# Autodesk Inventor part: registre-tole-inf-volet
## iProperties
Author: chr
Created: 2001-06
Part Number: registre-tole-inf-volet
Material: Par défaut
Document SubType Name: Tôlerie
Designer: chr
Control State: 0
Master: False
Checked Out: False
PropertySet Name: Design Tracking Control
Shininess: 21.0
PropertySet Name: _Private Model Information
Length Units: 11269
Angle Units: 11286
Time Units: 11279
Mass Units: 11290
Length Display Precision: 3
Angle Display Precision: 2
Compacted: False
Density: 0.0
Volumn: 0.0
Area: 0.0
PropertySet Name: Model Information
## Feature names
1. Ouverture1
2. Symétrie1 [Mirror]
3. Perçage1 [Hole]
4. Réseau rectangulaire1 [Rectangular Pattern]
5. Plaque1
6. Plaque2
7. Pli1
8. Plaque3
9. Pli2
